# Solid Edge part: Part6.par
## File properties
Author: Deepak Maini
Template: Normal.par
Last saved by: Robert a Rhodes jr
Revision: 2
Application: Solid Edge
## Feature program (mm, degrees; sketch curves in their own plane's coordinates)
body "unnamed Body 1"
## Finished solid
Body 1: solid body, 43 faces, 102 edges, 68 vertices.
  Faces by surface: cylinder 28, plane 15
  Edges by curve: circle 56, line 46
Bounding box of the edges (mm): 1353.852 x 457.200 x 1295.400, from (-676.9261, -203.2, -533.4) to (676.9261, 254, 762).
Cylindrical faces by radius (mm): R50.8 x6, R95.25 x6, R127 x5, R152.4 x2, R254 x2, R431.8 x2, R508 x2, R533.4 x3
Planar faces by outward normal: +x 1, +y 7, -x 1, -y 2, oblique 4
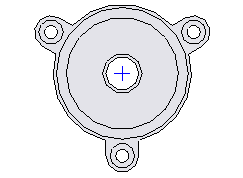
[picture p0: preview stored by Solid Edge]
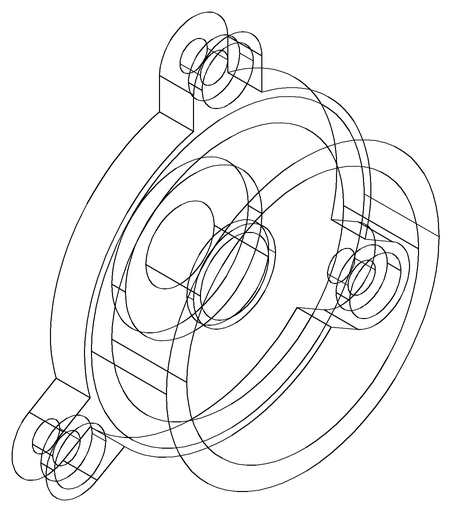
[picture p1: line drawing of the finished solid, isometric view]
